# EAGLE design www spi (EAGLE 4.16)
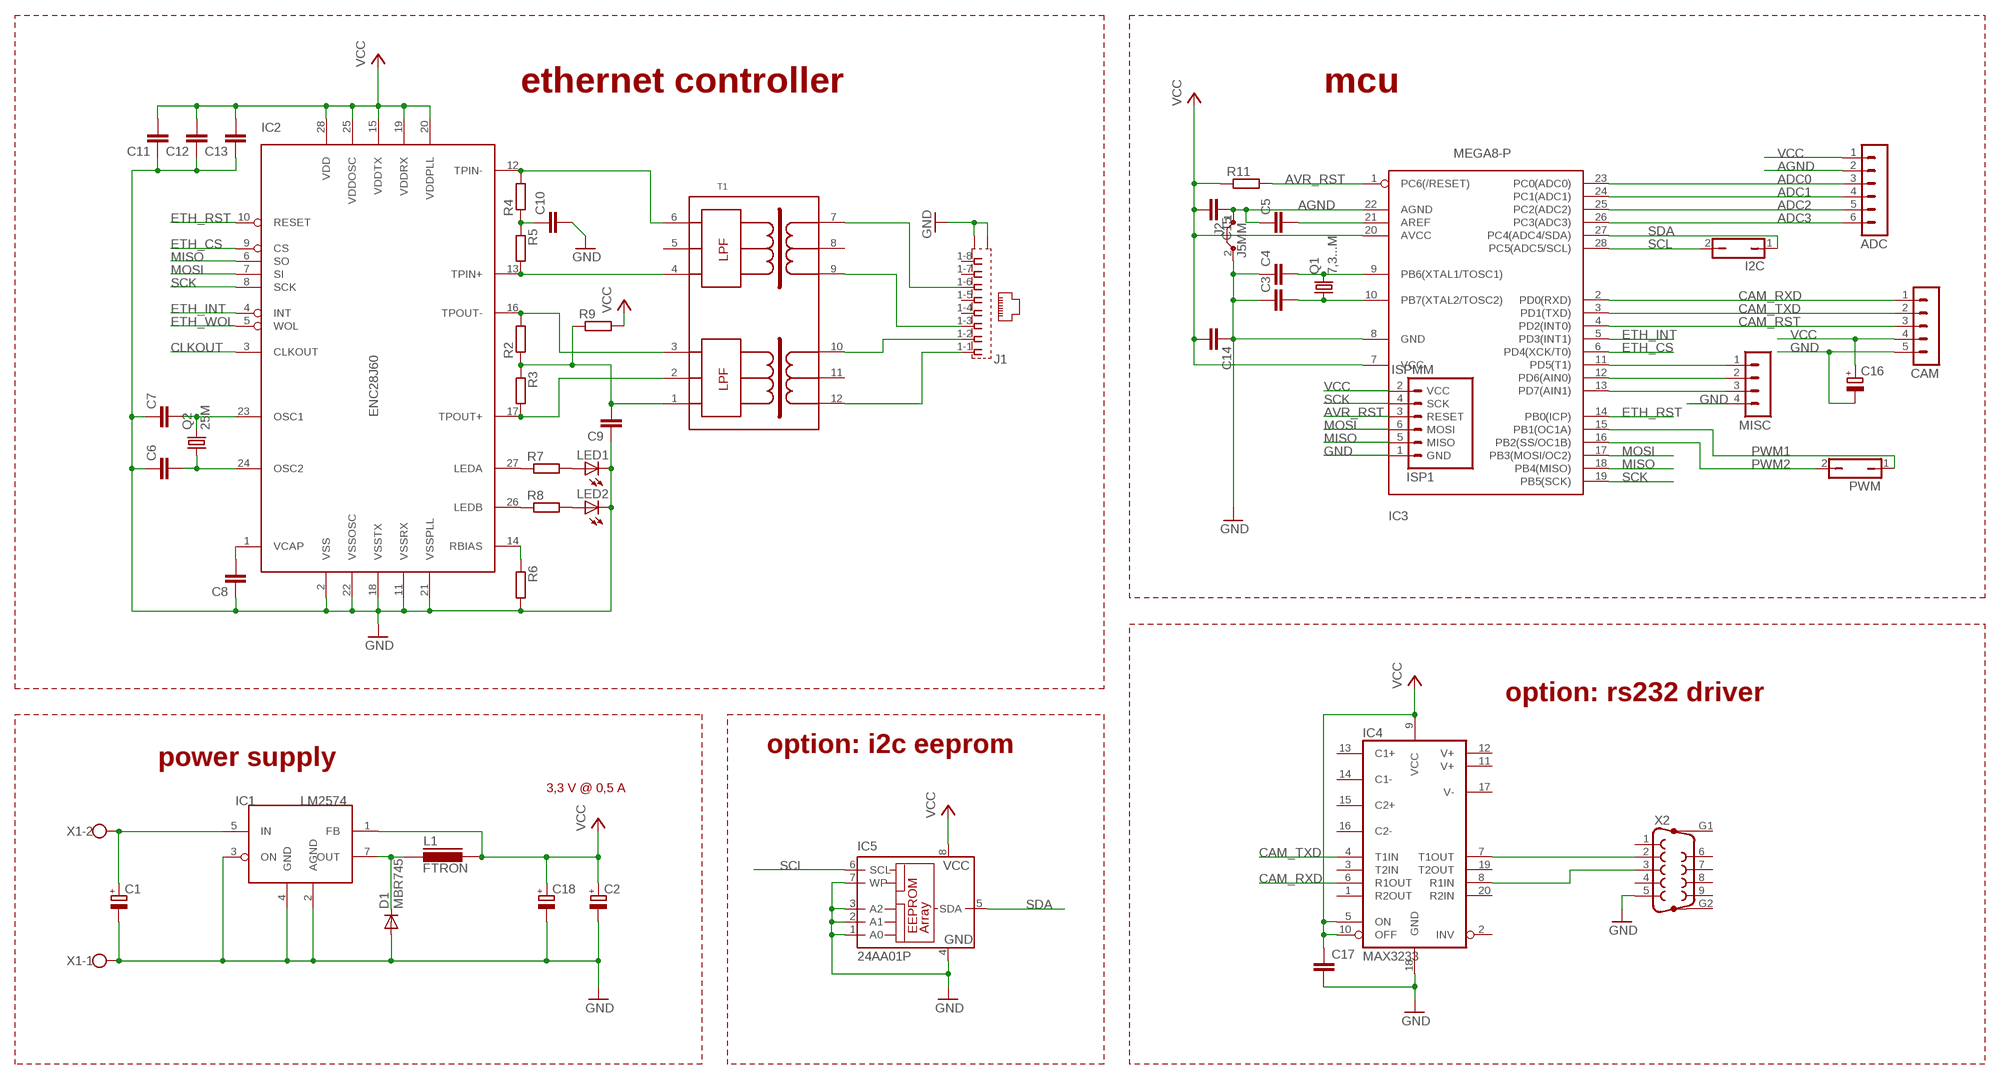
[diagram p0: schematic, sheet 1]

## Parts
ADC  MA06-1  [MA06-1]
C1  CPOL-EUE5-8.5  [E5-8,5]
C2  CPOL-EUE5-10.5  [E5-10,5]
C3  C-EU025-024X044  [C025-024X044]
C4  C-EU025-024X044  [C025-024X044]
C5  C2,5-3  [C2.5-3]
C6  C-EU025-024X044  [C025-024X044]
C7  C-EU025-024X044  [C025-024X044]
C8  C2,5-3  [C2.5-3]
C9  C5/3  [C5B3]
C10  C5/3  [C5B3]
C11  C2,5-3  [C2.5-3]
C12  C2,5-3  [C2.5-3]
C13  C2,5-3  [C2.5-3]
C14  C2,5-3  [C2.5-3]
C15  C5/2.5  [C5B2.5]
C16  CPOL-EUE2.5-5  [E2,5-5]
C17  C2,5-3  [C2.5-3]
C18  CPOL-EUE5-10.5  [E5-10,5]
CAM  MA05-1  [MA05-1]
D1  MBR745  [TO220ACS]
I2C  JP1Q  [JP1]
IC1  LM2574  [DIL08]
IC2  ENC28J60  [DIL28-3]
IC3  MEGA8-P  [DIL28-3]
IC4  MAX3233  [DIL20]
IC5  24AA01P  [DIL8]
ISP1  ISPMM  [MICROMATCH-6]
J1  557786-1  [557786-1]
J2  J5MM  [05]
L1  FTRON  [FTRON]
LED1  LED3MM  [LED3MM]
LED2  LED3MM  [LED3MM]
MISC  MA04-1  [MA04-1]
PWM  JP1Q  [JP1]
Q1  7,3...M  CRYTALHC49U70  [HC49U70]
Q2  25M  CRYTALHC49U70  [HC49U70]
R2  R-EU_0309/10  [0309/10]
R3  R-EU_0309/10  [0309/10]
R4  R-EU_0309/10  [0309/10]
R5  R-EU_0309/10  [0309/10]
R6  R-EU_0309/10  [0309/10]
R7  R-EU_0309/10  [0309/10]
R8  R-EU_0309/10  [0309/10]
R9  R-EU_0309/10  [0309/10]
R11  R-EU_0309/12  [0309/12]
T1  20F001  [DIL16/12]
X1  W237-02P  [W237-132]
X2  F09HP  [F09HP]

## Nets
ADC0: ADC.3 IC3.23(PC0(ADC0))
ADC1: ADC.4 IC3.24(PC1(ADC1))
ADC2: ADC.5 IC3.25(PC2(ADC2))
ADC3: ADC.6 IC3.26(PC3(ADC3))
AGND: ADC.2 C5.1 C15.1 IC3.22(AGND) J2.1
AVR_RST: IC3.1(PC6(/RESET)) ISP1.3(RESET) R11.2
CAM_RST: CAM.3 IC3.4(PD2(INT0))
CAM_RXD: CAM.1 IC3.2(PD0(RXD)) IC4.6(R1OUT)
CAM_TXD: CAM.2 IC3.3(PD1(TXD)) IC4.4(T1IN)
CLKOUT: IC2.3(CLKOUT)
ETH_CS: IC2.9(CS) IC3.6(PD4(XCK/T0))
ETH_INT: IC2.4(INT) IC3.5(PD3(INT1))
ETH_RST: IC2.10(RESET) IC3.14(PB0(ICP))
ETH_WOL: IC2.5(WOL)
GND: C1.- C2.- C3.1 C4.1 C6.1 C7.1 C8.1 C9.1 C10.2 C11.1 C12.1 C13.1 C14.1 C16.- C17.2 C18.- CAM.5 D1.A IC1.2(AGND) IC1.3(ON) IC1.4(GND) IC2.2(VSS) IC2.11(VSSRX) IC2.18(VSSTX) IC2.21(VSSPLL) IC2.22(VSSOSC) IC3.8(GND) IC4.18(GND) IC5.1(A0) IC5.2(A1) IC5.3(A2) IC5.4(GND) IC5.7(WP) ISP1.1(GND) J1.G1(S2) J1.G2(S1) J2.2 LED1.K(C) LED2.K(C) MISC.4 R6.2 X1.1 X2.5
MISO: IC2.6(SO) IC3.18(PB4(MISO)) ISP1.5(MISO)
MOSI: IC2.7(SI) IC3.17(PB3(MOSI/OC2)) ISP1.6(MOSI)
N$1: C10.1 R4.1 R5.1
N$2: C1.+ IC1.5(IN) X1.2
N$3: IC4.7(T1OUT) X2.2
N$4: IC2.27(LEDA) R7.1
N$6: IC4.8(R1IN) X2.3
N$7: IC2.26(LEDB) R8.1
N$8: C9.2 R2.1 R3.1 R9.1 T1.1
N$9: J1.1-1 T1.12
N$10: J1.1-2 T1.10
N$11: IC2.16(TPOUT-) R2.2 T1.3
N$12: IC3.11(PD5(T1)) MISC.1
N$13: C7.2 IC2.23(OSC1) Q2.2
N$14: C6.2 IC2.24(OSC2) Q2.1
N$15: C8.2 IC2.1(VCAP)
N$16: IC2.17(TPOUT+) R3.2 T1.2
N$17: IC2.12(TPIN-) R4.2 T1.6
N$18: IC2.13(TPIN+) R5.2 T1.4
N$19: IC2.14(RBIAS) R6.1
N$20: J1.1-3 T1.9
N$21: J1.1-6 T1.7
N$22: LED1.A R7.2
N$23: LED2.A R8.2
N$24: IC3.12(PD6(AIN0)) MISC.2
N$25: C3.2 IC3.10(PB7(XTAL2/TOSC2)) Q1.1
N$26: C4.2 IC3.9(PB6(XTAL1/TOSC1)) Q1.2
N$27: C5.2 IC3.21(AREF)
N$28: IC3.13(PD7(AIN1)) MISC.3
N$33: D1.C IC1.7(OUT) L1.1
PWM1: IC3.15(PB1(OC1A)) PWM.1
PWM2: IC3.16(PB2(SS/OC1B)) PWM.2
SCK: IC2.8(SCK) IC3.19(PB5(SCK)) ISP1.4(SCK)
SCL: I2C.2 IC3.28(PC5(ADC5/SCL)) IC5.6(SCL)
SDA: I2C.1 IC3.27(PC4(ADC4/SDA)) IC5.5(SDA)
VCC: ADC.1 C2.+ C11.2 C12.2 C13.2 C14.2 C15.2 C16.+ C17.1 C18.+ CAM.4 IC1.1(FB) IC2.15(VDDTX) IC2.19(VDDRX) IC2.20(VDDPLL) IC2.25(VDDOSC) IC2.28(VDD) IC3.7(VCC) IC3.20(AVCC) IC4.5(ON) IC4.9(VCC) IC4.10(OFF) IC5.8(VCC) ISP1.2(VCC) L1.2 R9.2 R11.1
Unconnected: IC4.1(R2OUT) IC4.2(INV) IC4.3(T2IN) IC4.11(V+) IC4.12(V+) IC4.13(C1+) IC4.14(C1-) IC4.15(C2+) IC4.16(C2-) IC4.17(V-) IC4.19(T2OUT) IC4.20(R2IN) J1.1-4 J1.1-5 J1.1-7 J1.1-8 T1.5 T1.8 T1.11 X2.1 X2.4 X2.6 X2.7 X2.8 X2.9 X2.G1 X2.G2

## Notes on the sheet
- ethernet controller | mcu
- option: rs232 driver
- option: i2c eeprom
- power supply
- 3,3 V @ 0,5 A

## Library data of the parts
ADC = con-lstb:MA06-1: PIN HEADER
C1 C2 C16 C18 = rcl:CPOL-EU: POLARIZED CAPACITOR, European symbol
C3 C4 C6 C7 = rcl:C-EU: CAPACITOR, European symbol
C5 C8-C15 C17 = capacitor-wima:C: CAPACITOR
CAM = con-lstb:MA05-1: PIN HEADER
D1 = 001:MBR745: DIODE
I2C PWM = jumper:JP1Q: JUMPER
IC1 = 001:LM2574
IC2 = 000:ENC28J60: MICROCONTROLLER 8 Kbytes FLASH 1 kbytes SRAM 512 bytes EEPROM USART 4-channel 10 bit ADC 2-channel 8 bit ADC
IC3 = atmel:MEGA8-P: MICROCONTROLLER 8 Kbytes FLASH 1 kbytes SRAM 512 bytes EEPROM USART 4-channel 10 bit ADC 2-channel 8 bit ADC Source: avr.lbr
IC4 = 000:MAX3233: RS232 TRANMITTER
IC5 = microchip:24*: Serial EEPROM I2C
ISP1 = 001:ISP: PIN HEADER
J1 = con-amp:557786-1: AMP connector
J2 = jumper:J: Bridge
L1 = 001:FTRON: INDUCTOR
LED1 LED2 = led:LED: LED
MISC = con-lstb:MA04-1: PIN HEADER
Q1 Q2 = crystal:CRYTAL: CRYSTAL
R2-R9 R11 = rcl:R-EU_: RESISTOR, European symbol
T1 = 000:20F001
X1 = con-wago-508:W237-02P: WAGO SREW CLAMP
X2 = con-subd:F09HP: SUB-D

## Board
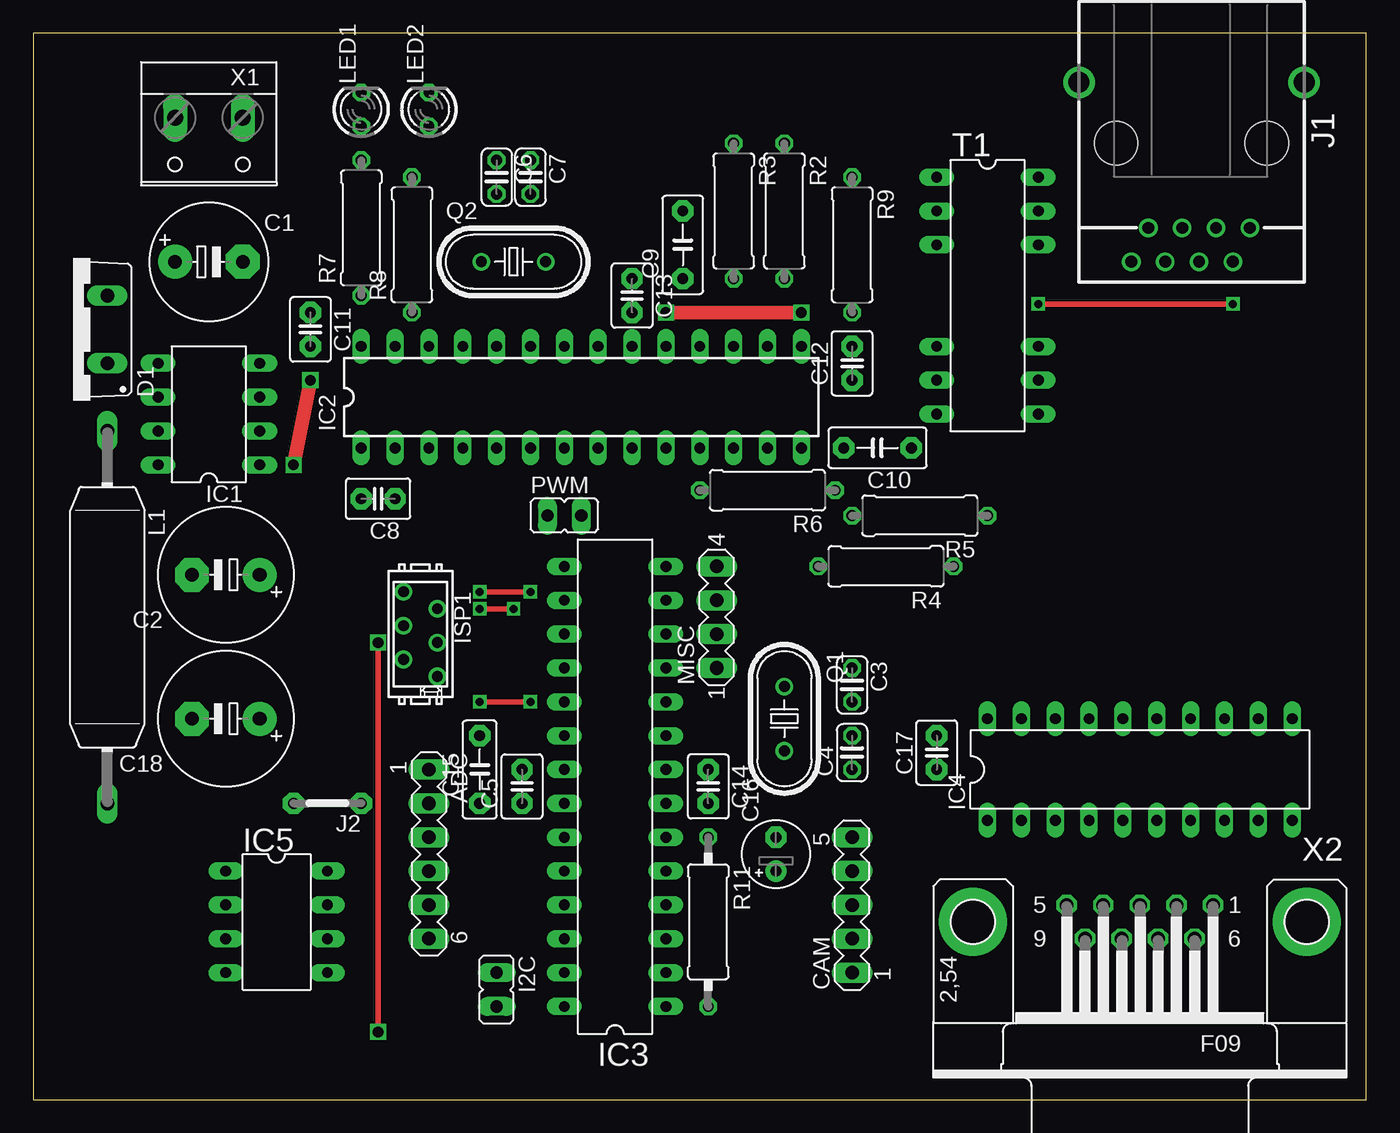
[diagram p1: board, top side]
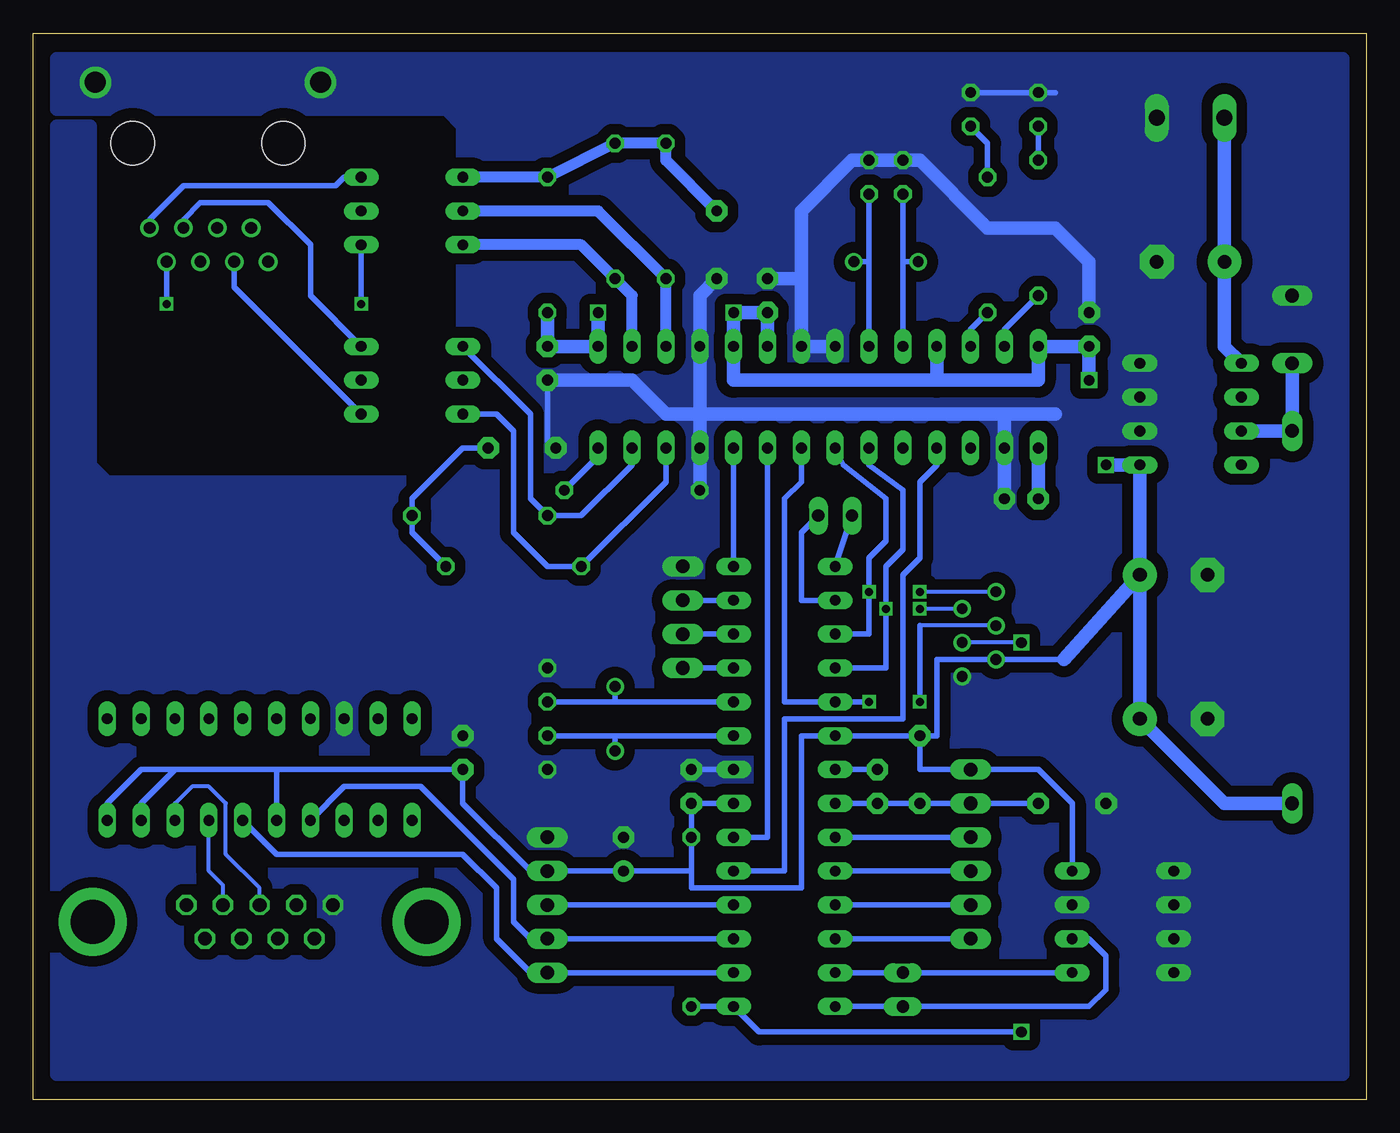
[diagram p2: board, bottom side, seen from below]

Size 100 x 80 mm. Coordinates in mm from the lower left corner, seen from the top.
Outline: 0,0 100,0 100,80 0,80 0,0
Copper layers (1*16): Top 0.035mm / dielectric 1.5mm / Bottom 0.035mm
Design rules "default": minimum track width 10mil, minimum drill 24mil, track to track 8mil, track to pad 8mil, pad to pad 8mil, via to via 8mil, smd to smd 8mil, copper to edge 40mil, drill to drill 8mil, minimum pad ring 10mil, minimum via ring 8mil, stop-mask expansion 4mil, vias tented up to drill 0mil, thermal gap 10mil

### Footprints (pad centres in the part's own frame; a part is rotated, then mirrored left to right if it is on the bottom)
MA06-1 = drill 1.016 long: 1 -6.35,0; 2 -3.81,0; 3 -1.27,0; 4 1.27,0; 5 3.81,0; 6 6.35,0
E5-8,5 = drill 1.016 pad 2.54 round: + -2.54,0 | drill 1.016 pad 2.54 octagon: - 2.54,0
E5-10,5 = drill 1.016 pad 2.54 round: + -2.54,0 | drill 1.016 pad 2.54 octagon: - 2.54,0
C025-024X044 = drill 0.813 octagon: 1 -1.27,0; 2 1.27,0
C2.5-3 = drill 0.813 pad 1.6 octagon: 1 -1.27,0; 2 1.27,0
C5B3 = drill 0.813 pad 1.6 octagon: 1 -2.54,0; 2 2.54,0
C5B2.5 = drill 0.813 pad 1.6 octagon: 1 -2.54,0; 2 2.54,0
E2,5-5 = drill 0.813 pad 1.6 round: + -1.27,0 | drill 0.813 pad 1.6 octagon: - 1.27,0
MA05-1 = drill 1.016 long: 1 -5.08,0; 2 -2.54,0; 3 0,0; 4 2.54,0; 5 5.08,0
TO220ACS = drill 1.016 long: A 2.54,-2.54; C -2.54,-2.54
JP1 = drill 0.914 long: 1 0,-1.27; 2 0,1.27
DIL08 = drill 0.813 long: 1 -3.81,-3.81; 2 -1.27,-3.81; 3 1.27,-3.81; 4 3.81,-3.81; 5 3.81,3.81; 6 1.27,3.81; 7 -1.27,3.81; 8 -3.81,3.81
DIL28-3 = drill 0.813 long: 1 -16.51,-3.81; 2 -13.97,-3.81; 3 -11.43,-3.81; 4 -8.89,-3.81; 5 -6.35,-3.81; 6 -3.81,-3.81; 7 -1.27,-3.81; 8 1.27,-3.81; 9 3.81,-3.81; 10 6.35,-3.81; 11 8.89,-3.81; 12 11.43,-3.81; 13 13.97,-3.81; 14 16.51,-3.81; 15 16.51,3.81; 16 13.97,3.81; 17 11.43,3.81; 18 8.89,3.81; 19 6.35,3.81; 20 3.81,3.81; 21 1.27,3.81; 22 -1.27,3.81; 23 -3.81,3.81; 24 -6.35,3.81; 25 -8.89,3.81; 26 -11.43,3.81; 27 -13.97,3.81; 28 -16.51,3.81
DIL20 = drill 0.813 long: 1 -11.43,-3.81; 2 -8.89,-3.81; 3 -6.35,-3.81; 4 -3.81,-3.81; 5 -1.27,-3.81; 6 1.27,-3.81; 7 3.81,-3.81; 8 6.35,-3.81; 9 8.89,-3.81; 10 11.43,-3.81; 11 11.43,3.81; 12 8.89,3.81; 13 6.35,3.81; 14 3.81,3.81; 15 1.27,3.81; 16 -1.27,3.81; 17 -3.81,3.81; 18 -6.35,3.81; 19 -8.89,3.81; 20 -11.43,3.81
DIL8 = drill 0.813 long: 1 -3.81,-3.81; 2 -1.27,-3.81; 3 1.27,-3.81; 4 3.81,-3.81; 5 3.81,3.81; 6 1.27,3.81; 7 -1.27,3.81; 8 -3.81,3.81
MICROMATCH-6 = drill 0.813 round: 1 3.175,1.27; 2 1.905,-1.27; 3 0.635,1.27; 4 -0.635,-1.27; 5 -1.905,1.27; 6 -3.175,-1.27
557786-1 = drill 0.889 round: 1-1 -4.445,6.35; 1-2 -3.175,8.89; 1-3 -1.905,6.35; 1-4 -0.635,8.89; 1-5 0.635,6.35; 1-6 1.905,8.89; 1-7 3.175,6.35; 1-8 4.445,8.89 | drill 1.575 pad 2.184 round: G1 -8.509,-4.572; G2 8.382,-4.572 | hole 3.251: -5.715,0; 5.588,0
05 = drill 0.813 pad 1.6 octagon: 1 -2.54,0; 2 2.54,0
FTRON = drill 1.016 long: 1 -12.7,0; 2 15.24,0
LED3MM = drill 0.813 octagon: A -1.27,0; K 1.27,0
MA04-1 = drill 1.016 long: 1 -3.81,0; 2 -1.27,0; 3 1.27,0; 4 3.81,0
HC49U70 = drill 0.813 round: 1 -2.413,0; 2 2.413,0
0309/10 = drill 0.813 octagon: 1 -5.08,0; 2 5.08,0
0309/12 = drill 0.813 octagon: 1 -6.35,0; 2 6.35,0
DIL16/12 = drill 0.813 long: 1 -8.89,-3.81; 2 -6.35,-3.81; 3 -3.81,-3.81; 4 3.81,-3.81; 5 6.35,-3.81; 6 8.89,-3.81; 7 8.89,3.81; 8 6.35,3.81; 9 3.81,3.81; 10 -3.81,3.81; 11 -6.35,3.81; 12 -8.89,3.81
W237-132 = drill 1.194 long: 1 -2.54,-0.635; 2 2.54,-0.635
F09HP = drill 1.016 octagon: 1 -5.486,-1.27; 2 -2.743,-1.27; 3 0,-1.27; 4 2.743,-1.27; 5 5.486,-1.27; 6 -4.115,1.27; 7 -1.372,1.27; 8 1.372,1.27; 9 4.115,1.27 | drill 3.302 pad 5.08 round: G1 -12.522,0; G2 12.522,0

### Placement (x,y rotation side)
ADC  29.68,18.41 270 top
C1  13.17,62.86 0 top
C2  14.44,39.37 180 top
C3  61.43,31.11 270 top
C4  61.43,26.03 90 top
C5  36.66,23.49 90 top
C6  34.76,69.21 270 top
C7  37.3,69.21 270 top
C8  25.87,45.08 180 top
C9  48.73,64.13 90 top
C10  63.34,48.89 180 top
C11  20.79,57.78 270 top
C12  61.43,55.24 90 top
C13  44.92,60.32 270 top
C14  50.63,23.49 270 top
C15  33.49,24.76 90 top
C16  55.71,18.41 90 top
C17  67.78,26.03 90 top
C18  14.44,28.57 180 top
CAM  61.43,14.6 90 top
D1  3.01,57.78 90 top
I2C  34.76,8.25 180 top
IC1  13.17,51.43 90 top
IC2  41.11,52.7 0 top
IC3  43.65,23.49 90 top
IC4  83.02,24.76 0 top
IC5  18.25,13.33 270 top
ISP1  29.04,34.92 270 top
J1  86.83,71.75 180 top
J2  22.06,22.22 180 top
L1  5.55,37.46 270 top
LED1  24.6,74.29 90 top
LED2  29.68,74.29 90 top
MISC  51.27,36.19 90 top
PWM  39.84,43.81 270 top
Q1  56.35,28.57 270 top
Q2  36.03,62.86 0 top
R2  56.35,66.67 270 top
R3  52.54,66.67 270 top
R4  63.97,40 180 top
R5  66.51,43.81 180 top
R6  55.08,45.72 180 top
R7  24.6,65.4 90 top
R8  28.41,64.13 90 top
R9  61.43,64.13 270 top
R11  50.63,13.33 270 top
T1  71.59,60.32 270 top
X1  13.17,73.02 180 top
X2  83.02,13.33 180 top

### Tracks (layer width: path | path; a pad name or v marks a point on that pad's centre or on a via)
ADC0
  Bottom 0.406: ADC.3 IC3.23
ADC1
  Bottom 0.406: ADC.4 IC3.24
ADC2
  Bottom 0.406: ADC.5 IC3.25
ADC3
  Bottom 0.406: ADC.6 IC3.26
AGND
  Bottom 0.406: 37.3,22.22 C5.1 | 37.3,22.22 IC3.22 | 37.3,22.22 C15.1 ADC.2 J2.1
AVR_RST  (via drill 0.8)
  Top 0.406: v25.87,5.08 v25.87,34.29
  Bottom 0.305: v25.87,34.29 ISP1.3
  Bottom 0.406: R11.2 IC3.1 45.55,5.08 v25.87,5.08
CAM_RST
  Bottom 0.406: IC3.4 CAM.3
CAM_RXD
  Bottom 0.406: IC3.2 CAM.1 62.7,9.52 65.24,12.06 65.24,15.87 67.78,18.41 81.75,18.41 IC4.6
CAM_TXD
  Bottom 0.406: IC3.3 CAM.2 62.7,12.06 63.97,13.33 63.97,16.5 70.95,23.49 76.67,23.49 IC4.4
ETH_CS
  Bottom 0.406: IC3.6 44.92,19.68 IC2.9
ETH_INT
  Bottom 0.406: IC3.5 43.65,17.14 43.65,28.57 34.76,28.57 34.76,39.37 33.49,40.64 33.49,46.35 32.22,47.62 IC2.4
ETH_RST
  Bottom 0.406: IC3.14 IC2.10
GND
  Bottom 0.406: C12.1 61.43,49.53 arc-90 C10.2 | LED2.K LED1.K 23.33,75.56 | IC3.8 C14.1
  Bottom 1.016: C8.1 IC2.2 27.14,51.43 | 27.14,51.43 23.33,51.43 | IC2.22 IC2.21 42.38,61.59 | 42.38,61.59 C13.1 | 42.38,61.59 42.38,66.67 38.57,70.48 C7.1 C6.1 33.49,70.48 28.41,65.4 23.33,65.4 20.79,62.86 C11.1 | 50,51.43 IC2.11 R6.2 | 27.14,51.43 50,51.43 | 50,51.43 IC2.18 50,60.32 C9.1 | 50,51.43 52.54,51.43 55.08,53.97 C12.1
  pour Bottom (isolate 0.813, no thermals): 1.74,78.1 98.26,78.1 98.26,74.29 69.05,74.29 67.78,73.02 67.78,47.62 69.05,46.35 94.45,46.35 95.72,47.62 95.72,73.02 98.26,73.02 98.26,1.9 1.74,1.9
MISO  (via drill 0.6)
  Top 0.406: v33.49,36.83 v36.03,36.83
  Bottom 0.305: ISP1.5 v33.49,36.83
  Bottom 0.406: IC2.6 37.3,47.62 34.76,45.72 34.76,41.27 36.03,40 v36.03,36.83 36.03,32.38 IC3.18
MOSI  (via drill 0.6)
  Top 0.406: v33.49,38.1 v37.3,38.1
  Bottom 0.305: ISP1.6 v33.49,38.1
  Bottom 0.406: IC2.7 39.2,47.62 36.03,45.08 36.03,41.91 37.3,40.64 v37.3,38.1 37.3,34.92 IC3.17
N$1
  Bottom 0.406: R4.1 71.59,42.54 R5.1 71.59,45.08 67.78,48.89 C10.1
N$2
  Bottom 1.016: IC1.5 10.63,56.51 C1.+ X1.2
N$3
  Bottom 0.305: IC4.7 86.83,17.14 85.76,16.07 X2.2
N$4
  Bottom 0.406: IC2.27 27.14,57.78 R7.1
N$6
  Bottom 0.305: IC4.8 89.37,22.22 88.1,23.49 86.83,23.49 85.56,22.22 85.56,18.41 83.02,15.87 X2.3
N$7
  Bottom 0.406: IC2.26 29.68,57.78 R8.1
N$8
  Bottom 0.813: C9.2 52.54,70.48 R3.1 R2.1 R9.1 T1.1
N$9
  Bottom 0.406: T1.12 76.67,69.21 77.3,68.57 88.73,68.57 91.28,66.03 J1.1-1
N$10  (via drill 0.6)
  Top 0.406: v75.4,59.69 v90,59.69
  Bottom 0.406: v75.4,59.69 T1.10 | v90,59.69 J1.1-2
N$11
  Bottom 0.813: IC2.16 55.08,60.32 R2.2 58.89,64.13 T1.3
N$12
  Bottom 0.406: IC3.11 MISC.1
N$13
  Bottom 0.406: 37.3,62.86 Q2.2 | 37.3,62.86 C7.2 | IC2.23 37.3,62.86
N$14
  Bottom 0.406: 34.76,62.86 Q2.1 | 34.76,62.86 C6.2 | IC2.24 34.76,62.86
N$15
  Bottom 1.016: C8.2 IC2.1
N$16
  Bottom 0.813: IC2.17 R3.2 57.62,66.67 T1.2
N$17
  Bottom 0.406: IC2.12 52.54,46.35 R4.2 61.43,40 63.97,42.54 63.97,50.16 65.24,51.43 T1.6
N$18
  Bottom 0.406: IC2.13 55.08,47.62 58.89,43.81 R5.2 62.7,45.08 62.7,51.43 T1.4
N$19
  Bottom 0.406: IC2.14 57.62,48.26 R6.1
N$20
  Bottom 0.406: T1.9 79.21,60.32 79.21,64.13 82.39,67.3 87.47,67.3 88.73,66.03 J1.1-3
N$21
  Bottom 0.406: T1.7 84.92,60.96 J1.1-6
N$22
  Bottom 0.406: R7.2 LED1.A
N$23
  Bottom 0.406: LED2.A 28.41,71.75 R8.2
N$24
  Bottom 0.406: IC3.12 MISC.2
N$25
  Bottom 0.406: 56.35,29.84 C3.2 | IC3.10 56.35,29.84 | 56.35,29.84 Q1.1
N$26
  Bottom 0.406: 56.35,27.3 C4.2 | IC3.9 56.35,27.3 | 56.35,27.3 Q1.2
N$27
  Bottom 0.406: C5.2 IC3.21
N$28
  Bottom 0.406: IC3.13 MISC.3
N$33
  Bottom 1.016: D1.C L1.1 IC1.7
PWM1
  Bottom 0.406: IC3.15 PWM.1
PWM2
  Bottom 0.406: IC3.16 42.38,37.46 42.38,42.54 PWM.2
SCK  (via drill 0.6)
  Top 0.406: v33.49,29.84 v37.3,29.84
  Bottom 0.305: ISP1.4 33.49,35.55
  Bottom 0.406: IC2.8 42.38,46.35 43.65,45.08 43.65,29.84 IC3.19 v37.3,29.84 | 33.49,35.55 v33.49,29.84
SCL
  Bottom 0.406: IC3.28 I2C.2 20.79,6.98 19.52,8.25 19.52,10.79 20.79,12.06 IC5.6
SDA
  Bottom 0.406: IC3.27 I2C.1 IC5.5
VCC  (via drill 0.8)
  Top 1.016: v47.46,59.05 v57.62,59.05 | v19.52,47.62 v20.79,53.97
  Bottom 0.406: 81.75,24.76 IC4.5 | IC4.10 94.45,22.22 91.91,24.76 89.37,24.76 | 81.75,24.76 89.37,24.76 | 89.37,24.76 91.91,22.22 IC4.9 | 81.75,24.76 C17.1 67.78,22.22 62.7,17.14 CAM.4 C16.+ 50.63,17.14 | IC3.7 C14.2 R11.1 50.63,17.14 | 50.63,17.14 50.63,15.87 42.38,15.87 42.38,27.3 IC3.20 C15.2 | IC5.8 22.06,22.22 24.6,24.76 ADC.1 33.49,24.76 C15.2 | 22.7,33.02 ISP1.2 32.22,33.02 32.22,27.3 C15.2
  Bottom 1.016: 32.22,53.97 IC2.25 | 32.22,53.97 24.6,53.97 IC2.28 C11.2 v20.79,53.97 | v57.62,59.05 IC2.15 C12.2 R9.2 | 32.22,53.97 47.46,53.97 IC2.19 v47.46,59.05 C13.2 IC2.20 | L1.2 10.63,22.22 C18.+ C2.+ | v19.52,47.62 IC1.1 C2.+ | C2.+ 22.7,33.02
